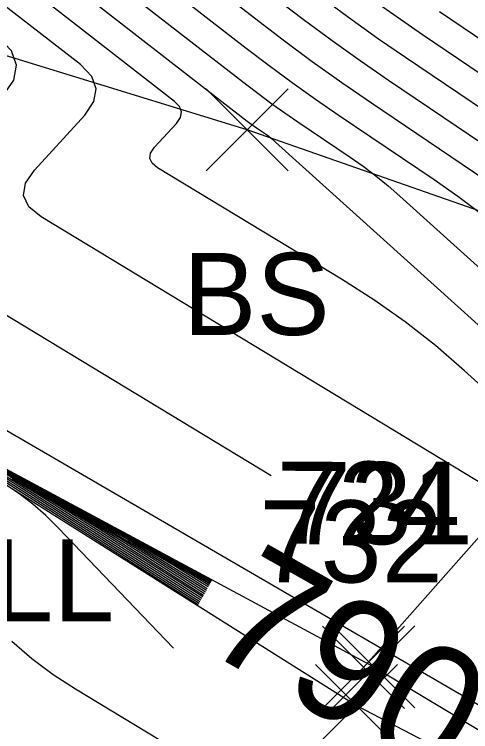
# Model space of a CAD drawing. Extents: x 1650836 to 1652450, y 332578 to 333908.
# Drawn here: x 1652088.94 to 1652100.04, y 332746.47 to 332763.95 of the extents above; entities that cross this region are included whole.
import ezdxf

# ---------------------------------------------------------------- set-up
doc = ezdxf.new("R2010")
doc.units = 0
for name, color, linetype in [('D_C', 7, 'Continuous'), ('D_I', 7, 'Continuous'), ('D_TIC', 7, 'Continuous'), ('DCP', 7, 'Continuous'), ('DHW', 7, 'Continuous'), ('L_A', 7, 'Continuous'), ('L_I', 7, 'Continuous'), ('L_TIC', 7, 'Continuous'), ('LELB', 7, 'Continuous'), ('LSOGCMA', 7, 'Continuous'), ('LSOGCMA_T', 7, 'Continuous'), ('LSOGCMI', 7, 'Continuous')]:
    doc.layers.add(name, color=color, linetype=linetype)

msp = doc.modelspace()

# ---------------------------------------------------------------- linework, layer by layer
at = {"layer": 'D_TIC'}
for points in [[(1652096.436, 332747.039), (1652098.436, 332749.039)], [(1652098.436, 332747.039), (1652096.436, 332749.039)], [(1652096.689, 332747.051), (1652098.689, 332749.051)], [(1652098.689, 332747.051), (1652096.689, 332749.051)]]:
    msp.add_lwpolyline(points, dxfattribs=at)
at = {"layer": 'DCP'}
msp.add_lwpolyline([(1652097.436, 332748.039), (1652173.064, 332833.561)], dxfattribs=at)
at = {"layer": 'DHW'}
for points in [[(1652082.217, 332757.601), (1652081.771, 332756.62), (1652097.689, 332748.051), (1652112.113, 332739.371), (1652112.479, 332739.998)], [(1652112.479, 332739.998), (1652082.217, 332757.601)]]:
    msp.add_lwpolyline(points, dxfattribs=at)
at = {"layer": 'L_TIC'}
for points in [[(1652093.604, 332760.138), (1652095.604, 332762.138)], [(1652095.604, 332760.138), (1652093.604, 332762.138)], [(1652096.265, 332746.108), (1652098.265, 332748.108)], [(1652098.265, 332746.108), (1652096.265, 332748.108)]]:
    msp.add_lwpolyline(points, dxfattribs=at)
at = {"layer": 'LELB'}
for points in [[(1652048.756, 332662.461), (1652082.555, 332678.298), (1652130.366, 332703.201), (1652148.083, 332715.406), (1652159.47, 332726.367), (1652148.02, 332734.227), (1652128.413, 332739.339), (1652116.951, 332747.33), (1652106.793, 332756.875), (1652094.604, 332761.138), (1652083.802, 332764.466), (1652074.482, 332770.284), (1652065.17, 332770.428), (1652062.989, 332774.387), (1652054.537, 332784.724), (1652034.993, 332796.475), (1652025.062, 332801.1), (1652009.772, 332808.074), (1651988.967, 332816.401), (1651980.006, 332832.954), (1651960.575, 332843.477), (1651932.852, 332862.75), (1651890.753, 332886.019), (1651847.527, 332911.35)], [(1652083.698, 332755.279), (1652086.382, 332753.968), (1652097.265, 332747.108), (1652108.096, 332741.456), (1652107.571, 332735.708), (1652094.748, 332723.239), (1652088.748, 332717.173), (1652080.101, 332708.542)]]:
    msp.add_lwpolyline(points, dxfattribs=at)
at = {"layer": 'LSOGCMA'}
for points in [[(1652108.605, 332748.825), (1652095.297, 332760.837), (1652095.243, 332760.884), (1652095.187, 332760.929), (1652095.13, 332760.972), (1652095.072, 332761.013), (1652094.834, 332761.174), (1652094.775, 332761.215), (1652094.717, 332761.256), (1652094.659, 332761.299), (1652094.602, 332761.343), (1652089.923, 332764.982)], [(1652093.733, 332750.134), (1652083.185, 332755.813)], [(1652088.62, 332752.815), (1652089.227, 332752.482), (1652089.827, 332752.137), (1652090.421, 332751.782), (1652091.009, 332751.415), (1652093.545, 332749.802)]]:
    msp.add_lwpolyline(points, dxfattribs=at)
at = {"layer": 'LSOGCMI'}
for points in [[(1652091.995, 332766.028), (1652094.779, 332763.862), (1652095.479, 332763.327), (1652096.188, 332762.803), (1652096.906, 332762.292), (1652097.632, 332761.792), (1652101.49, 332759.182)], [(1652091.304, 332765.679), (1652094.583, 332763.129), (1652095.138, 332762.705), (1652095.699, 332762.29), (1652096.268, 332761.885), (1652096.843, 332761.489), (1652099.157, 332759.924), (1652099.728, 332759.523), (1652100.284, 332759.103)], [(1652090.613, 332765.331), (1652094.593, 332762.236), (1652094.898, 332762.002), (1652095.208, 332761.773), (1652095.521, 332761.55), (1652095.838, 332761.331), (1652097.114, 332760.469), (1652097.429, 332760.248), (1652097.736, 332760.016), (1652098.034, 332759.774), (1652098.324, 332759.521), (1652108.164, 332750.639)], [(1652109.634, 332746.479), (1652099.898, 332755.268), (1652099.188, 332755.879), (1652098.452, 332756.454), (1652097.689, 332756.994), (1652096.899, 332757.499), (1652092.422, 332760.214), (1652092.291, 332760.321), (1652092.235, 332760.44), (1652092.255, 332760.57), (1652092.35, 332760.71), (1652092.883, 332761.294), (1652092.98, 332761.437), (1652093.005, 332761.574), (1652092.958, 332761.704), (1652092.838, 332761.829), (1652088.962, 332764.844)], [(1652095.191, 332752.704), (1652086.762, 332757.815), (1652086.29, 332758.203), (1652086.09, 332758.63), (1652086.162, 332759.096), (1652086.505, 332759.601), (1652088.667, 332761.969), (1652088.926, 332762.35), (1652088.992, 332762.715), (1652088.865, 332763.064), (1652088.545, 332763.396), (1652086.88, 332764.691)], [(1652101.342, 332751.89), (1652089.592, 332759.014), (1652089.29, 332759.262), (1652089.162, 332759.535), (1652089.208, 332759.833), (1652089.428, 332760.156), (1652090.652, 332761.497), (1652090.875, 332761.825), (1652090.932, 332762.139), (1652090.823, 332762.439), (1652090.547, 332762.725), (1652087.921, 332764.767)], [(1652095.333, 332764.318), (1652095.999, 332763.808), (1652096.673, 332763.311), (1652097.355, 332762.824), (1652098.045, 332762.349), (1652104.958, 332757.673)], [(1652096.518, 332764.29), (1652097.157, 332763.818), (1652097.804, 332763.357), (1652098.458, 332762.906), (1652104.898, 332758.55)], [(1652097.641, 332764.325), (1652098.253, 332763.889), (1652098.872, 332763.463), (1652104.96, 332759.345), (1652105.852, 332758.754), (1652106.755, 332758.18), (1652107.668, 332757.623), (1652108.592, 332757.084), (1652112.31, 332754.959), (1652113.249, 332754.447), (1652114.206, 332753.975), (1652115.181, 332753.542), (1652116.175, 332753.148), (1652123.836, 332750.287), (1652124.99, 332749.853), (1652126.143, 332749.417), (1652127.295, 332748.976), (1652128.445, 332748.533), (1652133.042, 332746.75), (1652134.188, 332746.298), (1652135.33, 332745.832), (1652136.465, 332745.354), (1652137.596, 332744.862)], [(1652099.285, 332764.02), (1652105.022, 332760.14), (1652105.862, 332759.583), (1652106.713, 332759.042), (1652107.574, 332758.518), (1652108.444, 332758.009), (1652111.947, 332756.007), (1652112.832, 332755.525), (1652113.734, 332755.08), (1652114.653, 332754.672), (1652115.589, 332754.3), (1652125.599, 332750.562), (1652126.649, 332750.168), (1652127.462, 332749.86)], [(1652093.751, 332750.167), (1652081.865, 332756.566)], [(1652093.748, 332750.161), (1652082.085, 332756.441)], [(1652093.745, 332750.156), (1652082.305, 332756.315)], [(1652093.742, 332750.15), (1652082.525, 332756.19)], [(1652093.739, 332750.145), (1652082.745, 332756.064)], [(1652093.736, 332750.139), (1652082.965, 332755.938)], [(1652093.726, 332750.122), (1652093.639, 332750.172), (1652093.191, 332750.419), (1652083.405, 332755.687)], [(1652093.713, 332750.1), (1652093.609, 332750.162), (1652093.107, 332750.451), (1652092.6, 332750.73), (1652083.626, 332755.561)], [(1652093.697, 332750.071), (1652093.689, 332750.076), (1652093.135, 332750.408), (1652092.575, 332750.729), (1652092.009, 332751.041), (1652083.846, 332755.436)], [(1652093.677, 332750.035), (1652093.273, 332750.287), (1652092.661, 332750.653), (1652092.043, 332751.008), (1652091.418, 332751.352), (1652084.066, 332755.31)], [(1652093.656, 332749.998), (1652093.52, 332750.084), (1652092.857, 332750.497), (1652092.188, 332750.898), (1652091.511, 332751.286), (1652090.827, 332751.663), (1652084.286, 332755.185)], [(1652084.506, 332755.059), (1652090.236, 332751.974), (1652090.979, 332751.565), (1652091.714, 332751.143), (1652092.441, 332750.708), (1652093.161, 332750.259), (1652093.633, 332749.959)], [(1652084.726, 332754.933), (1652089.645, 332752.285), (1652090.447, 332751.844), (1652091.24, 332751.388), (1652092.025, 332750.919), (1652092.802, 332750.435), (1652093.611, 332749.92)], [(1652084.946, 332754.808), (1652089.231, 332752.5), (1652090.004, 332752.075), (1652090.768, 332751.637), (1652091.525, 332751.184), (1652092.273, 332750.718), (1652093.589, 332749.881)], [(1652087.215, 332753.508), (1652093.412, 332749.568)], [(1652087.847, 332753.16), (1652093.434, 332749.607)], [(1652088.48, 332752.811), (1652093.456, 332749.646)], [(1652088.765, 332752.678), (1652089.112, 332752.462), (1652093.478, 332749.685)], [(1652088.838, 332752.685), (1652089.356, 332752.387), (1652089.869, 332752.08), (1652090.376, 332751.764), (1652093.522, 332749.763)], [(1652088.885, 332752.638), (1652089.317, 332752.379), (1652089.744, 332752.113), (1652093.5, 332749.724)], [(1652088.926, 332752.658), (1652089.615, 332752.279), (1652090.298, 332751.887), (1652090.973, 332751.483), (1652091.641, 332751.066), (1652093.567, 332749.842)], [(1652092.808, 332748.503), (1652090.007, 332751.437), (1652089.703, 332751.736), (1652089.384, 332752.015), (1652089.048, 332752.275), (1652088.695, 332752.514)], [(1652088.875, 332748.677), (1652089.366, 332748.256), (1652089.883, 332747.869), (1652090.427, 332747.514), (1652094.768, 332744.886)]]:
    msp.add_lwpolyline(points, dxfattribs=at)

# ---------------------------------------------------------------- texts
at = {"layer": 'D_C'}
msp.add_text('MARBLE HEAD WALL', height=2, dxfattribs=at).set_placement((1652064.177, 332749.161))
at = {"layer": 'D_I'}
for s, p in [('724', (1652095.327, 332751.051)), ('731', (1652095.641, 332751.039))]:
    msp.add_text(s, height=2, dxfattribs=at).set_placement(p)
at = {"layer": 'L_A'}
msp.add_text('BS', height=2, dxfattribs=at).set_placement((1652093.045, 332756.138))
at = {"layer": 'L_I'}
msp.add_text('732', height=2, dxfattribs=at).set_placement((1652094.903, 332750.108))
at = {"layer": 'LSOGCMA_T'}
msp.add_text('790', height=3, rotation=330.4332, dxfattribs=at).set_placement((1652093.449, 332748.532))

doc.saveas('drawing.dxf')
